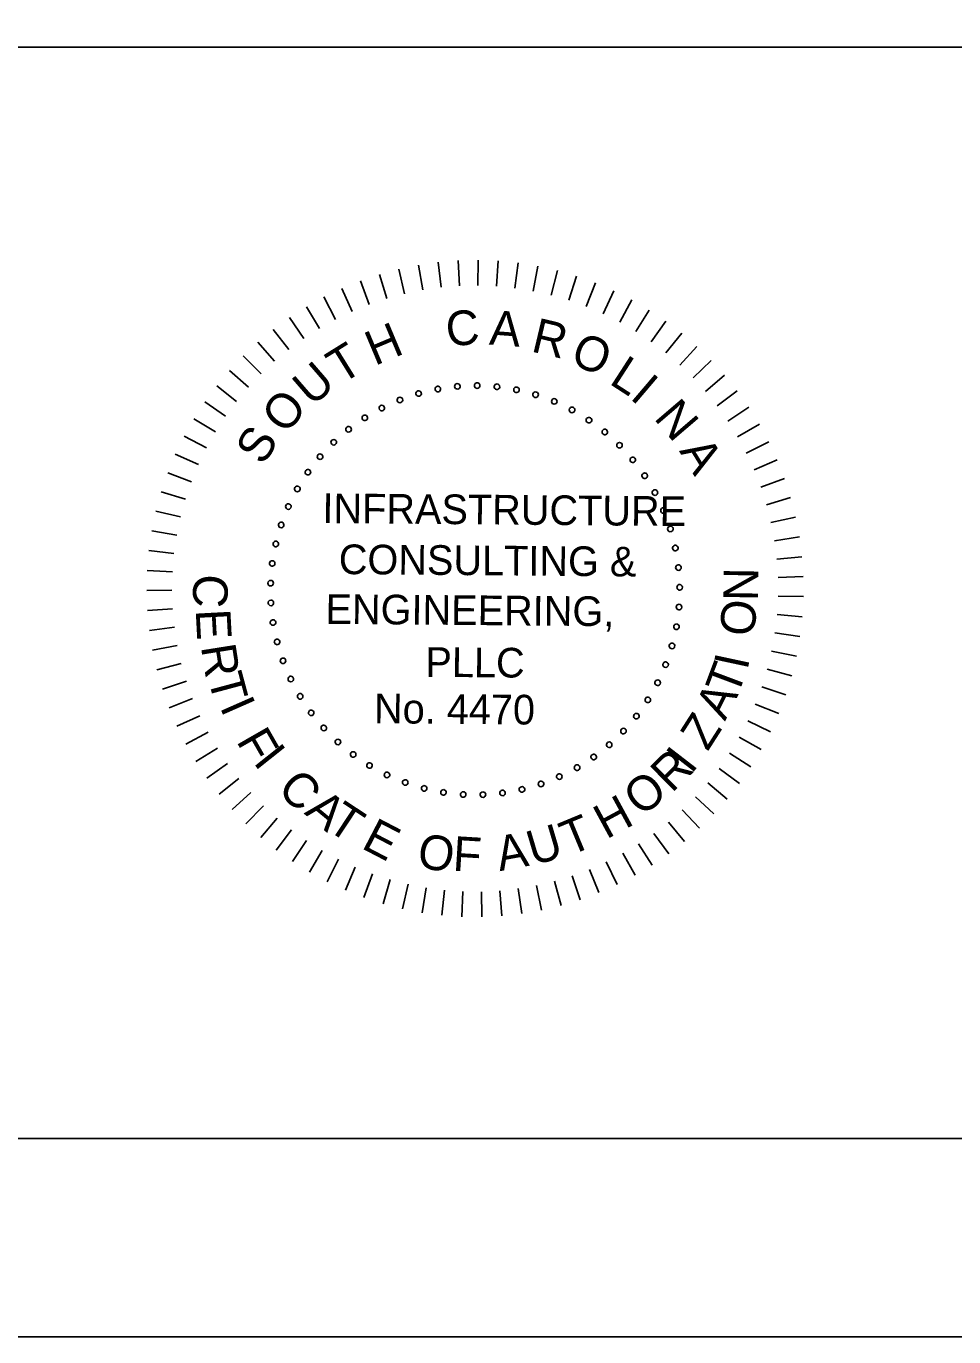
# Model space of a CAD drawing. Extents: x -383 to 3, y -322 to -94.
# Drawn here: x -204.37 to -195.02, y -187.49 to -174.28 of the extents above; entities that cross this region are included whole.
import ezdxf

# ---------------------------------------------------------------- set-up
doc = ezdxf.new("R2010")
doc.units = 0
for name, color, linetype in [('BR_BORDER LINES', 7, 'Continuous'), ('BR_TEXT', 7, 'Continuous'), ('Level 31', 7, 'Continuous')]:
    doc.layers.add(name, color=color, linetype=linetype)

msp = doc.modelspace()

# ---------------------------------------------------------------- linework, layer by layer
at = {"layer": 'BR_BORDER LINES'}
for p, q in [((-214.64, -174.489), (-193.18, -174.489)), ((-297.843, -185.489), (-163.178, -185.489))]:
    msp.add_line(p, q, dxfattribs=at)
at = {"layer": 'BR_TEXT'}
for p, q in [((-199.814, -176.636), (-199.816, -176.89)), ((-200.615, -176.726), (-200.555, -176.974)), ((-200.417, -176.685), (-200.373, -176.936)), ((-200.217, -176.656), (-200.188, -176.909)), ((-200.016, -176.64), (-200.002, -176.894)), ((-199.612, -176.644), (-199.63, -176.898)), ((-199.411, -176.664), (-199.444, -176.917)), ((-199.212, -176.697), (-199.26, -176.947)), ((-199.015, -176.741), (-199.079, -176.988)), ((-201.001, -176.844), (-200.912, -177.082)), ((-200.81, -176.779), (-200.735, -177.023)), ((-198.821, -176.798), (-198.9, -177.04)), ((-198.631, -176.866), (-198.724, -177.103)), ((-201.37, -177.007), (-201.252, -177.233)), ((-201.188, -176.92), (-201.084, -177.153)), ((-198.446, -176.946), (-198.553, -177.177)), ((-201.546, -177.106), (-201.415, -177.324)), ((-198.265, -177.037), (-198.387, -177.261)), ((-198.091, -177.139), (-198.226, -177.355)), ((-201.716, -177.215), (-201.572, -177.425)), ((-197.923, -177.251), (-198.071, -177.458)), ((-201.879, -177.334), (-201.723, -177.535)), ((-197.762, -177.373), (-197.922, -177.571)), ((-202.035, -177.463), (-201.866, -177.654)), ((-197.609, -177.505), (-197.781, -177.693)), ((-202.182, -177.601), (-202.002, -177.781)), ((-197.464, -177.646), (-197.647, -177.823)), ((-202.321, -177.748), (-202.13, -177.917)), ((-197.329, -177.795), (-197.522, -177.961)), ((-202.45, -177.903), (-202.25, -178.06)), ((-197.202, -177.952), (-197.405, -178.106)), ((-202.57, -178.065), (-202.36, -178.21)), ((-197.086, -178.117), (-197.298, -178.258)), ((-202.679, -178.235), (-202.461, -178.366)), ((-196.979, -178.289), (-197.199, -178.417)), ((-202.779, -178.411), (-202.553, -178.529)), ((-196.883, -178.467), (-197.111, -178.581)), ((-202.867, -178.593), (-202.634, -178.696)), ((-196.799, -178.65), (-197.033, -178.75)), ((-202.944, -178.779), (-202.705, -178.869)), ((-196.725, -178.838), (-196.965, -178.924)), ((-203.009, -178.97), (-202.766, -179.045)), ((-196.664, -179.03), (-196.908, -179.101)), ((-203.063, -179.165), (-202.815, -179.225)), ((-196.614, -179.226), (-196.862, -179.282)), ((-203.104, -179.363), (-202.853, -179.407)), ((-196.576, -179.424), (-196.827, -179.465)), ((-203.134, -179.562), (-202.881, -179.592)), ((-196.55, -179.625), (-196.804, -179.65)), ((-203.151, -179.764), (-202.897, -179.777)), ((-196.537, -179.826), (-196.791, -179.836)), ((-203.156, -179.965), (-202.901, -179.964)), ((-196.535, -180.028), (-196.79, -180.022)), ((-203.149, -180.167), (-202.895, -180.15)), ((-203.129, -180.368), (-202.877, -180.335)), ((-196.547, -180.23), (-196.8, -180.208)), ((-196.57, -180.43), (-196.822, -180.393)), ((-203.097, -180.568), (-202.847, -180.52)), ((-196.606, -180.629), (-196.855, -180.577)), ((-203.053, -180.765), (-202.807, -180.701)), ((-196.653, -180.825), (-196.899, -180.758)), ((-202.997, -180.959), (-202.755, -180.881)), ((-196.713, -181.018), (-196.954, -180.936)), ((-202.93, -181.149), (-202.693, -181.056)), ((-196.784, -181.207), (-197.02, -181.111)), ((-202.851, -181.335), (-202.62, -181.228)), ((-202.761, -181.516), (-202.536, -181.395)), ((-196.867, -181.392), (-197.096, -181.281)), ((-196.96, -181.57), (-197.182, -181.446)), ((-202.66, -181.69), (-202.443, -181.556)), ((-197.065, -181.743), (-197.279, -181.605)), ((-202.548, -181.859), (-202.34, -181.711)), ((-197.179, -181.91), (-197.385, -181.759)), ((-202.426, -182.02), (-202.228, -181.86)), ((-197.304, -182.068), (-197.5, -181.905)), ((-202.295, -182.173), (-202.107, -182.002)), ((-197.438, -182.219), (-197.623, -182.045)), ((-202.155, -182.319), (-201.977, -182.136)), ((-197.581, -182.362), (-197.756, -182.176)), ((-202.006, -182.455), (-201.84, -182.262)), ((-197.733, -182.495), (-197.895, -182.3)), ((-201.849, -182.582), (-201.695, -182.379)), ((-197.892, -182.62), (-198.042, -182.414)), ((-201.685, -182.699), (-201.543, -182.487)), ((-198.059, -182.734), (-198.196, -182.519)), ((-201.513, -182.806), (-201.385, -182.586)), ((-201.336, -182.903), (-201.221, -182.675)), ((-198.411, -182.93), (-198.522, -182.701)), ((-198.232, -182.837), (-198.356, -182.615)), ((-201.153, -182.988), (-201.053, -182.754)), ((-200.965, -183.062), (-200.879, -182.822)), ((-198.785, -183.083), (-198.867, -182.842)), ((-198.596, -183.012), (-198.692, -182.777)), ((-200.773, -183.125), (-200.702, -182.88)), ((-200.577, -183.175), (-200.521, -182.927)), ((-200.379, -183.214), (-200.338, -182.962)), ((-199.373, -183.223), (-199.41, -182.971)), ((-199.174, -183.188), (-199.226, -182.939)), ((-198.978, -183.142), (-199.045, -182.896)), ((-200.179, -183.24), (-200.154, -182.987)), ((-199.978, -183.254), (-199.968, -183)), ((-199.776, -183.256), (-199.781, -183.002)), ((-199.574, -183.246), (-199.595, -182.992))]:
    msp.add_line(p, q, dxfattribs=at)
for centre, start, end in [((-200.414, -177.98), 16.1422, 196.1422), ((-200.22, -177.935), 10.6038, 190.6038), ((-200.22, -177.935), 190.6038, 10.6038), ((-200.023, -177.908), 5.0653, 185.0653), ((-200.023, -177.908), 185.0653, 5.0653), ((-199.824, -177.9), 359.5268, 179.5268), ((-199.824, -177.9), 179.5268, 359.5268), ((-199.625, -177.912), 353.9884, 173.9884), ((-199.625, -177.912), 173.9884, 353.9884), ((-199.428, -177.943), 168.4499, 348.4499), ((-199.428, -177.943), 348.4499, 168.4499), ((-200.603, -178.045), 21.6807, 201.6807), ((-200.603, -178.045), 201.6807, 21.6807), ((-200.414, -177.98), 196.1422, 16.1422), ((-199.235, -177.992), 162.9114, 342.9114), ((-199.235, -177.992), 342.9114, 162.9114), ((-199.047, -178.06), 157.373, 337.373), ((-199.047, -178.06), 337.373, 157.373), ((-200.957, -178.226), 32.7576, 212.7576), ((-200.957, -178.226), 212.7576, 32.7576), ((-200.785, -178.127), 27.2191, 207.2191), ((-200.785, -178.127), 207.2191, 27.2191), ((-198.867, -178.146), 151.8345, 331.8345), ((-198.867, -178.146), 331.8345, 151.8345), ((-198.697, -178.249), 326.2961, 146.2961), ((-201.12, -178.341), 38.2961, 218.2961), ((-201.12, -178.341), 218.2961, 38.2961), ((-198.697, -178.249), 146.2961, 326.2961), ((-198.537, -178.368), 140.7576, 320.7576), ((-198.537, -178.368), 320.7576, 140.7576), ((-201.27, -178.472), 43.8345, 223.8345), ((-201.27, -178.472), 223.8345, 43.8345), ((-198.389, -178.502), 135.2191, 315.2191), ((-198.389, -178.502), 315.2191, 135.2191), ((-201.408, -178.617), 49.373, 229.373), ((-201.408, -178.617), 229.373, 49.373), ((-201.53, -178.774), 54.9114, 234.9114), ((-201.53, -178.774), 234.9114, 54.9114), ((-198.255, -178.649), 129.6807, 309.6807), ((-198.255, -178.649), 309.6807, 129.6807), ((-198.135, -178.809), 124.1422, 304.1422), ((-198.135, -178.809), 304.1422, 124.1422), ((-201.637, -178.942), 60.4499, 240.4499), ((-201.637, -178.942), 240.4499, 60.4499), ((-198.032, -178.979), 118.6038, 298.6038), ((-198.032, -178.979), 298.6038, 118.6038), ((-201.727, -179.12), 65.9884, 245.9884), ((-201.727, -179.12), 245.9884, 65.9884), ((-197.945, -179.159), 113.0653, 293.0653), ((-197.945, -179.159), 293.0653, 113.0653), ((-201.8, -179.305), 71.5268, 251.5268), ((-201.8, -179.305), 251.5268, 71.5268), ((-197.876, -179.346), 107.5268, 287.5268), ((-197.876, -179.346), 287.5268, 107.5268), ((-201.854, -179.497), 77.0653, 257.0653), ((-201.854, -179.497), 257.0653, 77.0653), ((-197.826, -179.538), 101.9884, 281.9884), ((-197.826, -179.538), 281.9884, 101.9884), ((-201.89, -179.693), 82.6038, 262.6038), ((-201.89, -179.693), 262.6038, 82.6038), ((-197.795, -179.735), 96.4499, 276.4499), ((-197.795, -179.735), 276.4499, 96.4499), ((-201.906, -179.892), 88.1422, 268.1422), ((-201.906, -179.892), 268.1422, 88.1422), ((-197.782, -179.934), 90.9114, 270.9114), ((-197.782, -179.934), 270.9114, 90.9114), ((-201.904, -180.091), 93.6807, 273.6807), ((-201.904, -180.091), 273.6807, 93.6807), ((-197.789, -180.133), 85.373, 265.373), ((-197.789, -180.133), 265.373, 85.373), ((-201.882, -180.289), 99.2191, 279.2191), ((-201.882, -180.289), 279.2191, 99.2191), ((-197.815, -180.331), 79.8345, 259.8345), ((-197.815, -180.331), 259.8345, 79.8345), ((-201.841, -180.484), 104.7576, 284.7576), ((-201.841, -180.484), 284.7576, 104.7576), ((-197.86, -180.525), 74.2961, 254.2961), ((-197.86, -180.525), 254.2961, 74.2961), ((-201.781, -180.675), 110.2961, 290.2961), ((-201.781, -180.675), 290.2961, 110.2961), ((-197.924, -180.714), 68.7576, 248.7576), ((-197.924, -180.714), 248.7576, 68.7576), ((-201.703, -180.858), 115.8345, 295.8345), ((-201.703, -180.858), 295.8345, 115.8345), ((-198.005, -180.896), 63.2191, 243.2191), ((-198.005, -180.896), 243.2191, 63.2191), ((-201.608, -181.033), 121.373, 301.373), ((-201.608, -181.033), 301.373, 121.373), ((-198.104, -181.069), 57.6807, 237.6807), ((-198.104, -181.069), 237.6807, 57.6807), ((-201.497, -181.199), 126.9114, 306.9114), ((-201.497, -181.199), 306.9114, 126.9114), ((-198.219, -181.232), 52.1422, 232.1422), ((-198.219, -181.232), 232.1422, 52.1422), ((-201.37, -181.352), 132.4499, 312.4499), ((-201.37, -181.352), 312.4499, 132.4499), ((-198.349, -181.383), 46.6038, 226.6038), ((-198.349, -181.383), 226.6038, 46.6038), ((-201.228, -181.493), 137.9884, 317.9884), ((-201.228, -181.493), 317.9884, 137.9884), ((-198.493, -181.521), 41.0653, 221.0653), ((-198.493, -181.521), 221.0653, 41.0653), ((-201.074, -181.619), 143.5268, 323.5268), ((-201.074, -181.619), 323.5268, 143.5268), ((-198.649, -181.644), 35.5268, 215.5268), ((-198.649, -181.644), 215.5268, 35.5268), ((-200.909, -181.73), 149.0653, 329.0653), ((-200.909, -181.73), 329.0653, 149.0653), ((-198.817, -181.752), 29.9884, 209.9884), ((-198.817, -181.752), 209.9884, 29.9884), ((-200.733, -181.825), 154.6038, 334.6038), ((-200.733, -181.825), 334.6038, 154.6038), ((-200.549, -181.902), 160.1422, 340.1422), ((-200.549, -181.902), 340.1422, 160.1422), ((-199.18, -181.916), 18.9114, 198.9114), ((-199.18, -181.916), 198.9114, 18.9114), ((-198.995, -181.842), 24.4499, 204.4499), ((-198.995, -181.842), 204.4499, 24.4499), ((-200.359, -181.961), 165.6807, 345.6807), ((-200.359, -181.961), 345.6807, 165.6807), ((-200.164, -182.001), 171.2191, 351.2191), ((-200.164, -182.001), 351.2191, 171.2191), ((-199.965, -182.022), 176.7576, 356.7576), ((-199.965, -182.022), 356.7576, 176.7576), ((-199.766, -182.024), 2.2961, 182.2961), ((-199.766, -182.024), 182.2961, 2.2961), ((-199.568, -182.007), 7.8345, 187.8345), ((-199.568, -182.007), 187.8345, 7.8345), ((-199.372, -181.971), 13.373, 193.373), ((-199.372, -181.971), 193.373, 13.373)]:
    msp.add_arc(centre, 0.028, start, end, dxfattribs=at)
at = {"layer": 'Level 31'}
msp.add_lwpolyline([(-305.176, -187.489), (-161.176, -187.489), (-161.176, -99.489), (-305.176, -99.489)], close=True, dxfattribs=at)

# ---------------------------------------------------------------- texts
at = {"layer": 'BR_TEXT'}
for s, height, rotation, p in [('C', 0.349, 4.7281, (-200.126, -177.506)), ('A', 0.349, 355.6981, (-199.708, -177.486)), ('H', 0.349, 22.7882, (-200.857, -177.704)), ('R', 0.349, 346.6681, (-199.291, -177.554)), ('O', 0.349, 337.638, (-198.9, -177.673)), ('T', 0.349, 31.8182, (-201.196, -177.894)), ('U', 0.349, 40.8482, (-201.49, -178.119)), ('L', 0.349, 327.108, (-198.504, -177.875)), ('I', 0.349, 319.578, (-198.294, -178.026)), ('O', 0.349, 49.8782, (-201.757, -178.403)), ('N', 0.349, 310.548, (-198.051, -178.23)), ('S', 0.349, 58.9083, (-201.979, -178.715)), ('A', 0.349, 301.5179, (-197.791, -178.559)), ('INFRASTRUCTURE', 0.29909, 359.5268, (-201.385, -179.286)), ('CONSULTING &', 0.29909, 359.5268, (-201.22, -179.8)), ('N', 0.349, 89.2085, (-196.993, -180.074)), ('C', 0.349, 267.025, (-202.679, -179.795)), ('ENGINEERING,', 0.29909, 359.5268, (-201.354, -180.302)), ('E', 0.349, 273.025, (-202.662, -180.161)), ('O', 0.349, 83.2085, (-197.038, -180.44)), ('R', 0.349, 279.025, (-202.61, -180.531)), ('PLLC', 0.2991, 359.5268, (-200.347, -180.836)), ('T', 0.349, 69.3954, (-197.203, -181.047)), ('I', 0.349, 77.9093, (-197.1, -180.777)), ('T', 0.349, 285.025, (-202.541, -180.846)), ('A', 0.349, 63.3954, (-197.326, -181.288)), ('I', 0.349, 293.7713, (-202.422, -181.138)), ('No. 4470', 0.2991, 359.5268, (-200.865, -181.304)), ('Z', 0.349, 57.3954, (-197.501, -181.594)), ('F', 0.349, 299.7713, (-202.257, -181.482)), ('I', 0.349, 308.5268, (-202.089, -181.698)), ('R', 0.349, 44.5268, (-197.863, -182.014)), ('I', 0.349, 52.3339, (-197.665, -181.825)), ('C', 0.349, 314.5268, (-201.851, -181.978)), ('O', 0.349, 38.5268, (-198.169, -182.254)), ('A', 0.349, 320.5268, (-201.575, -182.213)), ('H', 0.349, 28.5268, (-198.522, -182.478)), ('T', 0.349, 326.5268, (-201.357, -182.366)), ('E', 0.349, 332.5268, (-201.003, -182.558)), ('T', 0.349, 22.5268, (-198.894, -182.645)), ('O', 0.349, 350.5268, (-200.442, -182.753)), ('F', 0.349, 356.5268, (-200.076, -182.79)), ('A', 0.349, 10.5268, (-199.597, -182.796)), ('U', 0.349, 16.5268, (-199.261, -182.742))]:
    msp.add_text(s, height=height, rotation=rotation, dxfattribs=at).set_placement(p)

doc.saveas('drawing.dxf')
